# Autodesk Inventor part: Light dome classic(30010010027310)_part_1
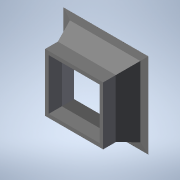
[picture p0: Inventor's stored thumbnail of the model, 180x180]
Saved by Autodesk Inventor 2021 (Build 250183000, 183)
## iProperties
Created: 2026-04
Part Number: Light dome classic(30010010027310)_part_1
Material: Generic
Catalog Web Link: www.3dfindit.com
Description: Light dome classic_part_1-
Vendor: KINGSPAN
Document SubType Name: Modeling
Designer: psAdmin
Manufacturer: KINGSPAN
Mass: 110789 g
Surface Area: 53147.3 cm^2
Volume: 110789 cm^3
Density: 1 g/cm^3
Appearance: PSOLRGB-255-255-255
Category: PARTsolutions
Company: KINGSPAN
Title: Light dome classic(30010010027310)_part_1
Author: Cadenas PARTsolutions
PSOL_IDENT_0: {$CADENAS_DATA/23d-libs/kingspan_kla/light_dome_classic/parts/part_1.prj},273 {VTYP=3D},{NB=Light do
PSOL_IDENT_1: me classic(30010010027310)_part_1},{LINA=Light dome classic(30010010027310)_part_1},{NN=Light dome c
PSOL_IDENT_2: lassic_part_1},{DATE=20.03.2025 09:30:52},{GEOMDATE=04.07.2024 05:40:44},{VERSION=},{LINEID=10},{WBV
PSOL_IDENT_3: AR=LODLEVEL,L,W,DP,OP,BA,INS,RT},{WBNUMERIC=W,RT}  {NB=Light dome classic(30010010027310)_part_1},{L
PSOL_IDENT_4: INA=Light dome classic(30010010027310)_part_1},{KT=DUMMY},{IDNR=},{PN=Light dome classic},{LODLEVEL=
PSOL_IDENT_5: 300},{L=100},{W=100},{DRIVE=1},{WX=100,150,200,250,300},{DP=2},{OP=7},{BA=3},{INS=1},{INSX='1','i -
PSOL_IDENT_6: insulation','2','ih - enhanced insulation'},{OPX='7','24/48 V OPEN/CLOSE including ventilation funct
PSOL_IDENT_7: ion'},{LX=1000},{XWX=1000},{HEI=1048.274},{BAX='2', 'PVC base 30 cm', '3', 'PVC base 50 cm' , '4', '
PSOL_IDENT_8: Metal base single skin (steel), 30 cm', '5' , 'Metal base single skin (steel), 40 cm', '6' , 'Metal
PSOL_IDENT_9: base single skin (steel), 50 cm', '7' , 'Metal base double skin (aluminum), 30 cm', '8' , 'Metal bas
PSOL_IDENT_10: e double skin (aluminum), 40 cm', '9' , 'Metal base double skin (aluminum), 50 cm', '10', 'Steel bas
PSOL_IDENT_11: e 30 cm', '11' , 'Steel base 40 cm', '12', 'Steel base 50 cm', '13' , 'AK30 AL/AL', '14' , 'AK40 AL/
PSOL_IDENT_12: AL', '15' , 'AK50 AL/AL', '16' , 'AK50 ST-TG'},{RT=0}
NB: Light dome classic(30010010027310)_part_1
NN: Light dome classic_part_1
NBSYN: $PN.($LODLEVEL.$L.$W.$DP.$OP.$BA.$INS.$RT.)_part_1
LINA: Light dome classic(30010010027310)_part_1
CATALOG: Light + Air
PN: Light dome classic
LODLEVEL: 300
L: 100
W: 100
DP: NSHEV (natural smoke, heat exhaust ventilation)
OP: 24/48 V OPEN/CLOSE including ventilation function
BA: PVC base 50 cm
INS: i - insulation
RT: 0
SUPPLIER: KINGSPAN
ARTICLENO: Light dome classic(30010010027310)_part_1
BOMINFO: Light dome classic(30010010027310)_part_1
CREATOR: CADENAS GmbH
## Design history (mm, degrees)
sketch "Sketch_1"
  geometry: L1 (-400.529, 500)-(-457.495, 500); L2 (-457.495, 500)-(-457.495, 300); L3 (-457.495, 300)-(-555.041, 12.062); L4 (-555.041, 12.062)-(-670.088, 1.996); L5 (-670.001, 0)-(-500, 0); L6 (-500, 0)-(-400.529, 293.622); L7 (-400.529, 293.622)-(-400.529, 500); A1 r 1 centre (-670.001, 1) between (-670.088, 1.996) and (-670.001, 0)
  constraints: 14 end point, 2 point on circle, 1 centre point
extrude "Extrusion1" join sketch "Sketch_1" stored distance "d0" = 2000; taper "d1" = 0 deg
sketch "Sketch_2"
  geometry: L1 (400.529, 500)-(400.529, 293.622); L2 (400.529, 293.622)-(500, 0); L3 (500, 0)-(670.001, 0); L4 (670.088, 1.996)-(555.041, 12.062); L5 (555.041, 12.062)-(457.495, 300); L6 (457.495, 300)-(457.495, 500); L7 (457.495, 500)-(400.529, 500); A1 r 1 centre (670.001, 1) between (670.001, 0) and (670.088, 1.996)
  constraints: 14 end point, 2 point on circle, 1 centre point
extrude "Extrusion2" join sketch "Sketch_2" stored distance "d2" = 2000; taper "d3" = 0 deg
sketch "Sketch_3"
  geometry: L1 (670.088, 1.996)-(555.041, 12.062); L2 (555.041, 12.062)-(457.495, 300); L3 (457.495, 300)-(457.495, 500); L4 (457.495, 500)-(400.529, 500); L5 (400.529, 500)-(400.529, 293.622); L6 (400.529, 293.622)-(500, 0); L7 (500, 0)-(670.001, 0); A1 r 1 centre (670.001, 1) between (670.001, 0) and (670.088, 1.996)
  constraints: 14 end point, 2 point on circle, 1 centre point
extrude "Extrusion3" join sketch "Sketch_3" stored distance "d4" = 2000; taper "d5" = 0 deg
sketch "Sketch_4"
  geometry: L1 (-400.529, 500)-(-457.495, 500); L2 (-457.495, 500)-(-457.495, 300); L3 (-457.495, 300)-(-555.041, 12.062); L4 (-555.041, 12.062)-(-670.088, 1.996); L5 (-670.001, 0)-(-500, 0); L6 (-500, 0)-(-400.529, 293.622); L7 (-400.529, 293.622)-(-400.529, 500); A1 r 1 centre (-670.001, 1) between (-670.088, 1.996) and (-670.001, 0)
  constraints: 14 end point, 2 point on circle, 1 centre point
extrude "Extrusion4" join sketch "Sketch_4" stored distance "d6" = 2000; taper "d7" = 0 deg
sketch "Sketch_5"
  geometry: L1 (-400, 600)-(-1000, 600); L2 (-1000, 600)-(-1000, -30); L3 (-1000, -30)-(-569.29, -30); L4 (-569.29, -30)-(-559.127, 0); L5 (-559.127, 0)-(-670.001, 0); L6 (-670.088, 1.996)-(-555.041, 12.062); L7 (-555.041, 12.062)-(-457.495, 300); L8 (-457.495, 300)-(-457.495, 500); L9 (-457.495, 500)-(-400, 500); L10 (-400, 500)-(-400, 600); A1 r 1 centre (-670.001, 1) between (-670.088, 1.996) and (-670.001, 0)
  constraints: 20 end point, 2 point on circle, 1 centre point
extrude "Extrusion5" cut sketch "Sketch_5" stored distance "d8" = 2000; taper "d9" = 0 deg
sketch "Sketch_6"
  geometry: L1 (1000, -30)-(1000, 600); L2 (1000, 600)-(400, 600); L3 (400, 600)-(400, 500); L4 (400, 500)-(457.495, 500); L5 (457.495, 500)-(457.495, 300); L6 (457.495, 300)-(555.041, 12.062); L7 (555.041, 12.062)-(670.088, 1.996); L8 (670.001, 0)-(559.127, 0); L9 (559.127, 0)-(569.29, -30); L10 (569.29, -30)-(1000, -30); A1 r 1 centre (670.001, 1) between (670.001, 0) and (670.088, 1.996)
  constraints: 20 end point, 2 point on circle, 1 centre point
extrude "Extrusion6" cut sketch "Sketch_6" stored distance "d10" = 2000; taper "d11" = 0 deg
sketch "Sketch_7"
  geometry: L1 (1000, 600)-(400, 600); L2 (400, 600)-(400, 500); L3 (400, 500)-(457.495, 500); L4 (457.495, 500)-(457.495, 300); L5 (457.495, 300)-(555.041, 12.062); L6 (555.041, 12.062)-(670.088, 1.996); L7 (670.001, 0)-(559.127, 0); L8 (559.127, 0)-(569.29, -30); L9 (569.29, -30)-(1000, -30); L10 (1000, -30)-(1000, 600); A1 r 1 centre (670.001, 1) between (670.001, 0) and (670.088, 1.996)
  constraints: 20 end point, 2 point on circle, 1 centre point
extrude "Extrusion7" cut sketch "Sketch_7" stored distance "d12" = 2000; taper "d13" = 0 deg
sketch "Sketch_9"
  geometry: L1 (-1000, 600)-(-1000, -30); L2 (-1000, -30)-(-569.29, -30); L3 (-569.29, -30)-(-559.127, 0); L4 (-559.127, 0)-(-670.001, 0); L5 (-670.088, 1.996)-(-555.041, 12.062); L6 (-555.041, 12.062)-(-457.495, 300); L7 (-457.495, 300)-(-457.495, 500); L8 (-457.495, 500)-(-400, 500); L9 (-400, 500)-(-400, 600); L10 (-400, 600)-(-1000, 600); A1 r 1 centre (-670.001, 1) between (-670.088, 1.996) and (-670.001, 0)
  constraints: 20 end point, 2 point on circle, 1 centre point
extrude "Extrusion8" cut sketch "Sketch_9" stored distance "d14" = 2000; taper "d15" = 0 deg
node "1_XY"
node "1_YZ"
node "1_ZX"
node "1_X"
node "1_Y"
node "1_Z"
node "1_Center"
node "IP_for_dummy_XY"
node "IP_for_dummy_YZ"
node "IP_for_dummy_ZX"
node "IP_for_dummy_X"
node "IP_for_dummy_Y"
node "IP_for_dummy_Z"
node "IP_for_dummy_Center"
node "IP_for_part_10_1_XY"
node "IP_for_part_10_1_YZ"
node "IP_for_part_10_1_ZX"
node "IP_for_part_10_1_X"
node "IP_for_part_10_1_Y"
node "IP_for_part_10_1_Z"
node "IP_for_part_10_1_Center"
node "IP_for_part_2_XY"
node "IP_for_part_2_YZ"
node "IP_for_part_2_ZX"
node "IP_for_part_2_X"
node "IP_for_part_2_Y"
node "IP_for_part_2_Z"
node "IP_for_part_2_Center"
node "light_dome_classic_XY"
node "light_dome_classic_YZ"
node "light_dome_classic_ZX"
node "light_dome_classic_X"
node "light_dome_classic_Y"
node "light_dome_classic_Z"
node "light_dome_classic_Center"
body "Solid1"
other parameters: "d16" = 0, "d17" = 0, "d18" = 0, "d19" = 0
